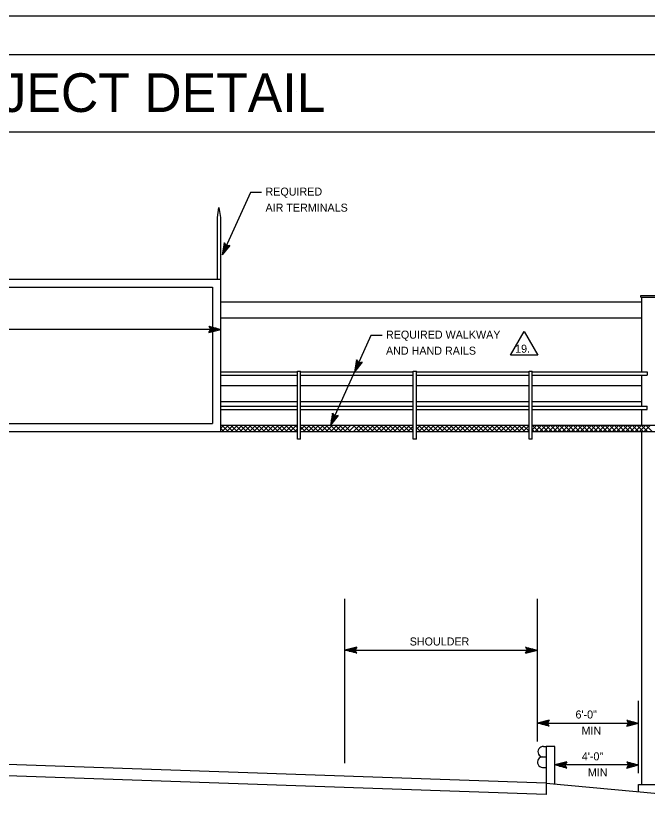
# Model space of a CAD drawing. Extents: x 515543 to 517243, y 661761 to 662861.
# Drawn here: x 516238 to 516646, y 662340 to 662861 of the extents above; entities that cross this region are included whole.
import ezdxf

# ---------------------------------------------------------------- set-up
doc = ezdxf.new("R2010")
doc.units = 0
for name, color, linetype in [('ANNO-SHT', 7, 'Continuous'), ('DRAINAGE', 7, 'Continuous'), ('Level 1', 7, 'Continuous'), ('Level 40', 7, 'Continuous'), ('Level 62', 7, 'Continuous'), ('Level 8', 7, 'Continuous'), ('LTT', 7, 'Continuous'), ('SHT-BDR', 7, 'Continuous'), ('SHT-BNDRY', 7, 'Continuous')]:
    doc.layers.add(name, color=color, linetype=linetype)

# ---------------------------------------------------------------- blocks, each defined once
blk = doc.blocks.new('SC47208')
at = {"layer": 'Level 1'}
blk.add_line((0, 0), (0, 0), dxfattribs=at)

msp = doc.modelspace()

# ---------------------------------------------------------------- linework, layer by layer
at = {"layer": 'Level 40'}
msp.add_lwpolyline([(516367.68, 662690.73), (516367.68, 662730.51), (516368.72, 662737.04), (516369.7, 662730.5), (516369.7, 662690.73)], dxfattribs=at)
at = {"layer": 'Level 62'}
msp.add_lwpolyline([(515542.51, 661760.72), (517242.52, 661760.72), (517242.52, 662860.72), (515542.51, 662860.72)], close=True, dxfattribs=at)
at = {"layer": 'Level 8'}
for p, q in [((516369.7, 662675.95), (516641.86, 662675.95)), ((516641.35, 662679.08), (516652.75, 662679.08)), ((516641.86, 662630.77), (516641.86, 662679.08)), ((516369.7, 662665.58), (516641.86, 662665.58)), ((516032.74, 662658.24), (516369.7, 662658.24)), ((516369.7, 662630.77), (516419.35, 662630.77)), ((516369.7, 662628.69), (516419.35, 662628.69)), ((516419.35, 662631.16), (516421.43, 662631.16)), ((516421.43, 662587.22), (516421.43, 662631.16)), ((516421.43, 662630.77), (516494.22, 662630.77)), ((516421.43, 662628.69), (516494.22, 662628.69)), ((516494.22, 662631.16), (516496.29, 662631.16)), ((516496.29, 662587.22), (516496.29, 662631.16)), ((516496.29, 662630.77), (516569.09, 662630.77)), ((516496.29, 662628.69), (516569.09, 662628.69)), ((516569.09, 662631.16), (516571.16, 662631.16)), ((516571.16, 662587.22), (516571.16, 662631.16)), ((516571.16, 662628.69), (516645.43, 662628.69)), ((516641.86, 662608.53), (516641.86, 662628.69)), ((516369.7, 662621.98), (516419.35, 662621.98)), ((516421.43, 662621.98), (516494.22, 662621.98)), ((516496.29, 662621.98), (516569.09, 662621.98)), ((516571.16, 662621.98), (516641.86, 662621.98)), ((516369.7, 662611.61), (516419.35, 662611.61)), ((516369.7, 662608.53), (516419.35, 662608.53)), ((516421.43, 662611.61), (516494.22, 662611.61)), ((516421.43, 662608.53), (516494.22, 662608.53)), ((516496.29, 662611.61), (516569.09, 662611.61)), ((516496.29, 662608.53), (516569.09, 662608.53)), ((516571.16, 662611.61), (516641.86, 662611.61)), ((516571.16, 662608.53), (516645.43, 662608.53)), ((516369.7, 662606.46), (516419.35, 662606.46)), ((516421.43, 662606.46), (516494.22, 662606.46)), ((516496.29, 662606.46), (516569.09, 662606.46)), ((516641.86, 662596.32), (516641.86, 662606.46)), ((516037.93, 662597.42), (516364.52, 662597.42)), ((516032.74, 662592.24), (516369.7, 662592.24)), ((516369.7, 662596.32), (516419.35, 662596.32)), ((516369.7, 662594.1), (516371.93, 662596.32)), ((516369.7, 662594.3), (516371.77, 662592.24)), ((516369.7, 662592.24), (516419.35, 662592.24)), ((516370.62, 662596.32), (516374.7, 662592.24)), ((516370.78, 662592.24), (516374.86, 662596.32)), ((516373.55, 662596.32), (516377.63, 662592.24)), ((516373.71, 662592.24), (516377.79, 662596.32)), ((516376.48, 662596.32), (516380.56, 662592.24)), ((516376.64, 662592.24), (516380.73, 662596.32)), ((516379.41, 662596.32), (516383.5, 662592.24)), ((516379.58, 662592.24), (516383.66, 662596.32)), ((516382.35, 662596.32), (516386.43, 662592.24)), ((516382.51, 662592.24), (516386.59, 662596.32)), ((516385.28, 662596.32), (516389.36, 662592.24)), ((516385.44, 662592.24), (516389.52, 662596.32)), ((516388.21, 662596.32), (516392.29, 662592.24)), ((516388.37, 662592.24), (516392.46, 662596.32)), ((516391.14, 662596.32), (516395.23, 662592.24)), ((516391.31, 662592.24), (516395.39, 662596.32)), ((516394.08, 662596.32), (516398.16, 662592.24)), ((516394.24, 662592.24), (516398.32, 662596.32)), ((516397.01, 662596.32), (516401.09, 662592.24)), ((516397.17, 662592.24), (516401.25, 662596.32)), ((516399.94, 662596.32), (516404.02, 662592.24)), ((516400.1, 662592.24), (516404.19, 662596.32)), ((516402.87, 662596.32), (516406.96, 662592.24)), ((516403.04, 662592.24), (516407.12, 662596.32)), ((516405.81, 662596.32), (516409.89, 662592.24)), ((516405.97, 662592.24), (516410.05, 662596.32)), ((516408.74, 662596.32), (516412.82, 662592.24)), ((516408.9, 662592.24), (516412.98, 662596.32)), ((516411.67, 662596.32), (516415.75, 662592.24)), ((516411.83, 662592.24), (516415.92, 662596.32)), ((516414.6, 662596.32), (516418.69, 662592.24)), ((516414.77, 662592.24), (516418.85, 662596.32)), ((516417.54, 662596.32), (516419.35, 662594.51)), ((516417.7, 662592.24), (516419.35, 662593.89)), ((516421.43, 662596.32), (516494.22, 662596.32)), ((516421.43, 662596.2), (516421.55, 662596.32)), ((516421.43, 662593.27), (516424.48, 662596.32)), ((516421.43, 662595.13), (516424.32, 662592.24)), ((516421.43, 662592.24), (516494.22, 662592.24)), ((516423.17, 662596.32), (516427.25, 662592.24)), ((516423.33, 662592.24), (516427.41, 662596.32)), ((516426.1, 662596.32), (516430.18, 662592.24)), ((516426.26, 662592.24), (516430.35, 662596.32)), ((516429.03, 662596.32), (516433.12, 662592.24)), ((516429.2, 662592.24), (516433.28, 662596.32)), ((516431.97, 662596.32), (516436.05, 662592.24)), ((516432.13, 662592.24), (516436.21, 662596.32)), ((516434.9, 662596.32), (516438.98, 662592.24)), ((516435.06, 662592.24), (516439.14, 662596.32)), ((516437.83, 662596.32), (516441.91, 662592.24)), ((516437.99, 662592.24), (516442.08, 662596.32)), ((516440.76, 662596.32), (516444.85, 662592.24)), ((516440.93, 662592.24), (516445.01, 662596.32)), ((516443.7, 662596.32), (516447.78, 662592.24)), ((516443.86, 662592.24), (516447.94, 662596.32)), ((516446.63, 662596.32), (516450.71, 662592.24)), ((516446.79, 662592.24), (516450.87, 662596.32)), ((516449.56, 662596.32), (516453.64, 662592.24)), ((516449.72, 662592.24), (516453.81, 662596.32)), ((516452.66, 662592.24), (516456.74, 662596.32)), ((516455.43, 662596.32), (516459.51, 662592.24)), ((516455.59, 662592.24), (516459.67, 662596.32)), ((516458.36, 662596.32), (516462.44, 662592.24)), ((516458.52, 662592.24), (516462.6, 662596.32)), ((516461.29, 662596.32), (516465.37, 662592.24)), ((516461.45, 662592.24), (516465.54, 662596.32)), ((516464.22, 662596.32), (516468.31, 662592.24)), ((516464.39, 662592.24), (516468.47, 662596.32)), ((516467.16, 662596.32), (516471.24, 662592.24)), ((516467.32, 662592.24), (516471.4, 662596.32)), ((516470.09, 662596.32), (516474.17, 662592.24)), ((516470.25, 662592.24), (516474.33, 662596.32)), ((516473.02, 662596.32), (516477.1, 662592.24)), ((516473.18, 662592.24), (516477.27, 662596.32)), ((516475.95, 662596.32), (516480.04, 662592.24)), ((516476.12, 662592.24), (516480.2, 662596.32)), ((516478.89, 662596.32), (516482.97, 662592.24)), ((516479.05, 662592.24), (516483.13, 662596.32)), ((516481.82, 662596.32), (516485.9, 662592.24)), ((516481.98, 662592.24), (516486.06, 662596.32)), ((516484.75, 662596.32), (516488.83, 662592.24)), ((516484.91, 662592.24), (516489, 662596.32)), ((516487.68, 662596.32), (516491.77, 662592.24)), ((516487.85, 662592.24), (516491.93, 662596.32)), ((516490.62, 662596.32), (516494.22, 662592.72)), ((516490.78, 662592.24), (516494.22, 662595.68)), ((516493.55, 662596.32), (516494.22, 662595.65)), ((516493.71, 662592.24), (516494.22, 662592.75)), ((516496.29, 662596.32), (516569.09, 662596.32)), ((516496.29, 662593.64), (516498.98, 662596.32)), ((516496.29, 662594.76), (516498.82, 662592.24)), ((516496.29, 662592.24), (516569.09, 662592.24)), ((516497.66, 662596.32), (516501.75, 662592.24)), ((516497.83, 662592.24), (516501.91, 662596.32)), ((516500.6, 662596.32), (516504.68, 662592.24)), ((516500.76, 662592.24), (516504.84, 662596.32)), ((516503.53, 662596.32), (516507.61, 662592.24)), ((516503.69, 662592.24), (516507.77, 662596.32)), ((516506.46, 662596.32), (516510.55, 662592.24)), ((516506.62, 662592.24), (516510.71, 662596.32)), ((516509.39, 662596.32), (516513.48, 662592.24)), ((516509.56, 662592.24), (516513.64, 662596.32)), ((516512.33, 662596.32), (516516.41, 662592.24)), ((516512.49, 662592.24), (516516.57, 662596.32)), ((516515.26, 662596.32), (516519.34, 662592.24)), ((516515.42, 662592.24), (516519.5, 662596.32)), ((516518.19, 662596.32), (516522.28, 662592.24)), ((516518.35, 662592.24), (516522.44, 662596.32)), ((516521.13, 662596.32), (516525.21, 662592.24)), ((516521.29, 662592.24), (516525.37, 662596.32)), ((516524.06, 662596.32), (516528.14, 662592.24)), ((516524.22, 662592.24), (516528.3, 662596.32)), ((516526.99, 662596.32), (516531.07, 662592.24)), ((516527.15, 662592.24), (516531.23, 662596.32)), ((516529.92, 662596.32), (516534.01, 662592.24)), ((516530.08, 662592.24), (516534.17, 662596.32)), ((516532.86, 662596.32), (516536.94, 662592.24)), ((516533.02, 662592.24), (516537.1, 662596.32)), ((516535.79, 662596.32), (516539.87, 662592.24)), ((516535.95, 662592.24), (516540.03, 662596.32)), ((516538.72, 662596.32), (516542.8, 662592.24)), ((516538.88, 662592.24), (516542.96, 662596.32)), ((516541.65, 662596.32), (516545.74, 662592.24)), ((516541.81, 662592.24), (516545.9, 662596.32)), ((516544.59, 662596.32), (516548.67, 662592.24)), ((516544.75, 662592.24), (516548.83, 662596.32)), ((516547.52, 662596.32), (516551.6, 662592.24)), ((516547.68, 662592.24), (516551.76, 662596.32)), ((516550.45, 662596.32), (516554.53, 662592.24)), ((516550.61, 662592.24), (516554.69, 662596.32)), ((516553.38, 662596.32), (516557.47, 662592.24)), ((516553.54, 662592.24), (516557.63, 662596.32)), ((516556.32, 662596.32), (516560.4, 662592.24)), ((516556.48, 662592.24), (516560.56, 662596.32)), ((516559.25, 662596.32), (516563.33, 662592.24)), ((516559.41, 662592.24), (516563.49, 662596.32)), ((516562.18, 662596.32), (516566.26, 662592.24)), ((516562.34, 662592.24), (516566.42, 662596.32)), ((516565.11, 662596.32), (516569.09, 662592.35)), ((516565.27, 662592.24), (516569.09, 662596.05)), ((516568.05, 662596.32), (516569.09, 662595.28)), ((516568.21, 662592.24), (516569.09, 662593.12)), ((516571.16, 662596.32), (516658.3, 662596.32)), ((516571.16, 662596.22), (516571.26, 662596.32)), ((516571.16, 662593.29), (516574.19, 662596.32)), ((516571.16, 662593.41), (516572.33, 662592.24)), ((516571.16, 662592.24), (516658.3, 662592.24)), ((516571.18, 662596.32), (516575.26, 662592.24)), ((516573.04, 662592.24), (516577.12, 662596.32)), ((516574.11, 662596.32), (516578.19, 662592.24)), ((516575.97, 662592.24), (516580.05, 662596.32)), ((516577.04, 662596.32), (516581.12, 662592.24)), ((516578.9, 662592.24), (516582.99, 662596.32)), ((516579.97, 662596.32), (516584.06, 662592.24)), ((516581.84, 662592.24), (516585.92, 662596.32)), ((516582.91, 662596.32), (516586.99, 662592.24)), ((516584.77, 662592.24), (516588.85, 662596.32)), ((516585.84, 662596.32), (516589.92, 662592.24)), ((516587.7, 662592.24), (516591.78, 662596.32)), ((516588.77, 662596.32), (516592.85, 662592.24)), ((516590.63, 662592.24), (516594.72, 662596.32)), ((516591.7, 662596.32), (516595.79, 662592.24)), ((516593.57, 662592.24), (516597.65, 662596.32)), ((516594.64, 662596.32), (516598.72, 662592.24)), ((516596.5, 662592.24), (516600.58, 662596.32)), ((516597.57, 662596.32), (516601.65, 662592.24)), ((516599.43, 662592.24), (516603.51, 662596.32)), ((516600.5, 662596.32), (516604.58, 662592.24)), ((516602.36, 662592.24), (516606.45, 662596.32)), ((516603.43, 662596.32), (516607.52, 662592.24)), ((516605.3, 662592.24), (516609.38, 662596.32)), ((516606.37, 662596.32), (516610.45, 662592.24)), ((516608.23, 662592.24), (516612.31, 662596.32)), ((516609.3, 662596.32), (516613.38, 662592.24)), ((516611.16, 662592.24), (516615.24, 662596.32)), ((516612.23, 662596.32), (516616.31, 662592.24)), ((516614.09, 662592.24), (516618.18, 662596.32)), ((516615.16, 662596.32), (516619.25, 662592.24)), ((516617.03, 662592.24), (516621.11, 662596.32)), ((516618.1, 662596.32), (516622.18, 662592.24)), ((516619.96, 662592.24), (516624.04, 662596.32)), ((516621.03, 662596.32), (516625.11, 662592.24)), ((516622.89, 662592.24), (516626.97, 662596.32)), ((516623.96, 662596.32), (516628.04, 662592.24)), ((516625.82, 662592.24), (516629.91, 662596.32)), ((516626.89, 662596.32), (516630.98, 662592.24)), ((516628.76, 662592.24), (516632.84, 662596.32)), ((516629.83, 662596.32), (516633.91, 662592.24)), ((516631.69, 662592.24), (516635.77, 662596.32)), ((516632.76, 662596.32), (516636.84, 662592.24)), ((516634.62, 662592.24), (516638.7, 662596.32)), ((516635.69, 662596.32), (516639.77, 662592.24)), ((516637.55, 662592.24), (516641.64, 662596.32)), ((516638.62, 662596.32), (516642.71, 662592.24)), ((516640.49, 662592.24), (516644.57, 662596.32)), ((516641.56, 662596.32), (516645.64, 662592.24)), ((516641.86, 662363.97), (516641.86, 662592.24)), ((516643.42, 662592.24), (516647.5, 662596.32)), ((516644.49, 662596.32), (516648.57, 662592.24)), ((516450.06, 662377.74), (516450.06, 662484.06)), ((516574.47, 662391.84), (516574.47, 662484.06)), ((516450.06, 662450.88), (516574.47, 662450.88)), ((516574.47, 662403.68), (516639.79, 662403.68)), ((516578.38, 662388.56), (516580.14, 662388.63)), ((516578.04, 662381.8), (516580.14, 662381.8)), ((516577.69, 662375.04), (516580.14, 662375.04)), ((516639.8, 662376.62), (516585.81, 662376.62)), ((516639.79, 662359.34), (516639.79, 662363.97)), ((516639.79, 662363.97), (516654.31, 662363.97))]:
    msp.add_line(p, q, dxfattribs=at)
for points in [[(516396.27, 662746.72), (516389.05, 662746.72), (516370.83, 662706.33)], [(516032.74, 662690.73), (516369.7, 662690.73), (516369.7, 662592.24)], [(516037.93, 662685.55), (516364.52, 662685.55), (516364.52, 662597.42)], [(516641.35, 662679.08), (516641.35, 662680.12), (516652.75, 662680.12), (516652.75, 662679.08)], [(516474.12, 662654.25), (516466.9, 662654.25), (516440.76, 662596.32)], [(516421.43, 662587.22), (516419.35, 662587.22), (516419.35, 662631.16)], [(516496.29, 662587.22), (516494.22, 662587.22), (516494.22, 662631.16)], [(516571.16, 662587.22), (516569.09, 662587.22), (516569.09, 662631.16)], [(516571.16, 662630.77), (516645.43, 662630.77), (516645.43, 662628.69)], [(516571.16, 662606.46), (516645.43, 662606.46), (516645.43, 662608.53)], [(516585.8, 662364.29), (516585.8, 662388.63), (516580.14, 662388.63), (516580.14, 662364.81)], [(516580.14, 662364.81), (516764.49, 662347.89), (516803.44, 662347.89)]]:
    msp.add_lwpolyline(points, dxfattribs=at)
for centre in [(516578.2, 662385.18), (516577.86, 662378.42)]:
    msp.add_arc(centre, 3.38, 86.9581, 267.2203, dxfattribs=at)
at = {"layer": 'LTT'}
for points in [[(516372.16, 662714.12), (516370.83, 662706.33)], [(516375.79, 662712.48), (516370.83, 662706.33)], [(516373.41, 662712.06), (516371.38, 662709.22), (516372.97, 662712.73), (516371.89, 662711.86), (516372.42, 662713.05), (516372.16, 662714.12), (516373.46, 662712.17)], [(516373.41, 662712.06), (516372.63, 662708.66), (516374.21, 662712.17), (516374.27, 662710.78), (516374.81, 662711.97), (516375.79, 662712.48), (516373.46, 662712.17)], [(516363.56, 662658.21), (516366.98, 662658.89), (516363.12, 662658.89), (516364.37, 662659.51), (516363.06, 662659.51), (516362.19, 662660.2), (516363.43, 662658.21)], [(516362.19, 662660.2), (516369.84, 662658.21)], [(516363.56, 662658.21), (516366.98, 662657.52), (516363.12, 662657.52), (516364.37, 662656.9), (516363.06, 662656.9), (516362.19, 662656.22), (516363.43, 662658.21)], [(516362.19, 662656.22), (516369.84, 662658.21)], [(516457.64, 662638.56), (516456.31, 662630.77)], [(516458.89, 662636.49), (516456.86, 662633.66), (516458.45, 662637.17), (516457.37, 662636.29), (516457.9, 662637.49), (516457.64, 662638.56), (516458.94, 662636.61)], [(516461.27, 662636.92), (516456.31, 662630.77)], [(516458.89, 662636.49), (516458.11, 662633.09), (516459.69, 662636.61), (516459.75, 662635.22), (516460.29, 662636.41), (516461.27, 662636.92), (516458.94, 662636.61)], [(516442.09, 662604.11), (516440.76, 662596.32)], [(516445.72, 662602.48), (516440.76, 662596.32)], [(516443.34, 662602.05), (516441.31, 662599.21), (516442.9, 662602.73), (516441.82, 662601.85), (516442.36, 662603.04), (516442.09, 662604.11), (516443.4, 662602.16)], [(516443.34, 662602.05), (516442.56, 662598.65), (516444.15, 662602.16), (516444.2, 662600.77), (516444.74, 662601.96), (516445.72, 662602.48), (516443.4, 662602.16)], [(516457.71, 662452.87), (516450.06, 662450.88)], [(516456.34, 662450.88), (516452.92, 662451.56), (516456.77, 662451.56), (516455.53, 662452.18), (516456.84, 662452.18), (516457.71, 662452.87), (516456.46, 662450.88)], [(516568.19, 662450.88), (516571.61, 662451.56), (516567.75, 662451.56), (516569, 662452.18), (516567.69, 662452.18), (516566.82, 662452.87), (516568.06, 662450.88)], [(516566.82, 662452.87), (516574.47, 662450.88)], [(516457.71, 662448.89), (516450.06, 662450.88)], [(516456.34, 662450.88), (516452.92, 662450.19), (516456.77, 662450.19), (516455.53, 662449.57), (516456.84, 662449.57), (516457.71, 662448.89), (516456.46, 662450.88)], [(516568.19, 662450.88), (516571.61, 662450.19), (516567.75, 662450.19), (516569, 662449.57), (516567.69, 662449.57), (516566.82, 662448.89), (516568.06, 662450.88)], [(516566.82, 662448.89), (516574.47, 662450.88)], [(516582.12, 662405.67), (516574.47, 662403.68)], [(516580.75, 662403.68), (516577.33, 662404.36), (516581.19, 662404.36), (516579.95, 662404.99), (516581.25, 662404.99), (516582.12, 662405.67), (516580.88, 662403.68)], [(516633.51, 662403.68), (516636.93, 662404.36), (516633.07, 662404.36), (516634.32, 662404.99), (516633.01, 662404.99), (516632.14, 662405.67), (516633.38, 662403.68)], [(516632.14, 662405.67), (516639.79, 662403.68)], [(516582.12, 662401.69), (516574.47, 662403.68)], [(516580.75, 662403.68), (516577.33, 662403), (516581.19, 662403), (516579.95, 662402.37), (516581.25, 662402.37), (516582.12, 662401.69), (516580.88, 662403.68)], [(516633.51, 662403.68), (516636.93, 662403), (516633.07, 662403), (516634.32, 662402.37), (516633.01, 662402.37), (516632.14, 662401.69), (516633.38, 662403.68)], [(516632.14, 662401.69), (516639.79, 662403.68)], [(516593.46, 662378.61), (516585.81, 662376.62)], [(516592.09, 662376.62), (516588.67, 662377.3), (516592.53, 662377.3), (516591.28, 662377.92), (516592.59, 662377.92), (516593.46, 662378.61), (516592.22, 662376.62)], [(516633.51, 662376.62), (516636.93, 662377.3), (516633.08, 662377.3), (516634.32, 662377.92), (516633.02, 662377.92), (516632.14, 662378.61), (516633.39, 662376.62)], [(516632.14, 662378.61), (516639.8, 662376.62)], [(516593.46, 662374.63), (516585.81, 662376.62)], [(516592.09, 662376.62), (516588.67, 662375.93), (516592.53, 662375.93), (516591.28, 662375.31), (516592.59, 662375.31), (516593.46, 662374.63), (516592.22, 662376.62)], [(516633.51, 662376.62), (516636.93, 662375.93), (516633.08, 662375.93), (516634.32, 662375.31), (516633.02, 662375.31), (516632.14, 662374.63), (516633.39, 662376.62)], [(516632.14, 662374.63), (516639.8, 662376.62)]]:
    msp.add_lwpolyline(points, dxfattribs=at)
at = {"layer": 'SHT-BDR'}
msp.add_lwpolyline([(515667.5, 661835.77), (517167.5, 661835.77), (517167.5, 662785.77), (515667.5, 662785.77)], close=True, dxfattribs=at)
at = {"layer": 'SHT-BNDRY'}
for p, q in [((516639.79, 662371.4), (516639.79, 662418.01)), ((516580.14, 662364.81), (516198.62, 662378.13)), ((516580.14, 662357.48), (516198.62, 662370.8)), ((516580.14, 662364.81), (516580.14, 662357.48))]:
    msp.add_line(p, q, dxfattribs=at)
for points in [[(515605.01, 661785.72), (517217.52, 661785.72), (517217.52, 662835.72), (515605.01, 662835.72)], [(516557.06, 662641.45), (516565.96, 662656.87), (516574.68, 662641.45)]]:
    msp.add_lwpolyline(points, close=True, dxfattribs=at)

# ---------------------------------------------------------------- block references
at = {"layer": 'DRAINAGE', "xscale": 1.0000020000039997, "yscale": 1.0000020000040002, "rotation": -116.41666666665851}
msp.add_blockref('SC47208', (516419.1, 662811.71), dxfattribs=at)
msp.add_blockref('SC47208', (516419.1, 662811.71), dxfattribs=at)

# ---------------------------------------------------------------- texts
at = {"layer": 'ANNO-SHT'}
msp.add_text('         SPECIAL PROJECT DETAIL         ', height=24.9975, dxfattribs=at).set_placement((515921.08, 662798.73))
at = {"layer": 'Level 8'}
for s, p in [('REQUIRED', (516398.78, 662744.67)), ('AIR TERMINALS', (516398.78, 662734.3)), ('REQUIRED WALKWAY', (516476.63, 662652.21)), ('AND HAND RAILS', (516476.63, 662641.84)), ('19. ', (516560.06, 662643.1)), ('SHOULDER', (516491.96, 662453.86)), ('6\'-0"', (516599.08, 662406.66)), ('MIN', (516602.98, 662396.29))]:
    msp.add_text(s, height=5.184, rotation=360, dxfattribs=at).set_placement(p)
for s, p in [('4\'-0"', (516603.16, 662379.6)), ('MIN', (516607.06, 662369.23))]:
    msp.add_text(s, height=5.184, dxfattribs=at).set_placement(p)

doc.saveas('drawing.dxf')
